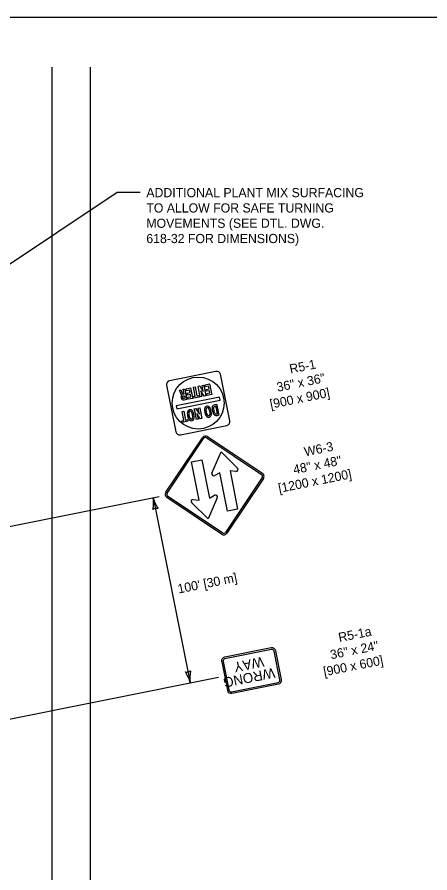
# Model space of a CAD drawing. Extents: x 49991.4 to 50021, y 49987.6 to 50011.4.
# Drawn here: x 50008.26 to 50010.96, y 49993.41 to 49999 of the extents above; entities that cross this region are included whole.
import ezdxf

# ---------------------------------------------------------------- set-up
doc = ezdxf.new("R2010")
doc.units = 0
for name, color, linetype in [('Level 1', 7, 'Continuous'), ('Level 2', 7, 'Continuous'), ('Level 3', 7, 'Continuous')]:
    doc.layers.add(name, color=color, linetype=linetype)

msp = doc.modelspace()

# ---------------------------------------------------------------- linework, layer by layer
at = {"layer": 'Level 1'}
for p, q in [((50008.4852, 49998.6725), (50008.4852, 49988.1855)), ((50008.7352, 49998.6725), (50008.7352, 49988.1855)), ((50009.5569, 49996.6843), (50009.2531, 49996.6231)), ((50009.6479, 49996.3607), (50009.5866, 49996.6648)), ((50009.2335, 49996.5936), (50009.2948, 49996.2896)), ((50009.3195, 49996.5619), (50009.3285, 49996.5641)), ((50009.3211, 49996.5577), (50009.3195, 49996.5619)), ((50009.3211, 49996.5577), (50009.3211, 49996.5577)), ((50009.3211, 49996.5577), (50009.3211, 49996.5577)), ((50009.324, 49996.5487), (50009.3211, 49996.5577)), ((50009.3285, 49996.5641), (50009.3361, 49996.5409)), ((50009.3435, 49996.567), (50009.3522, 49996.5686)), ((50009.3492, 49996.5382), (50009.3435, 49996.567)), ((50009.3522, 49996.5686), (50009.353, 49996.5641)), ((50009.353, 49996.5641), (50009.3548, 49996.555)), ((50009.3616, 49996.5706), (50009.391, 49996.5767)), ((50009.3644, 49996.5576), (50009.3616, 49996.5706)), ((50009.3849, 49996.5616), (50009.3644, 49996.5576)), ((50009.3883, 49996.5453), (50009.3849, 49996.5616)), ((50009.391, 49996.5767), (50009.3924, 49996.5682)), ((50009.3924, 49996.5682), (50009.3972, 49996.5446)), ((50009.4101, 49996.5804), (50009.421, 49996.5825)), ((50009.4218, 49996.5217), (50009.4101, 49996.5804)), ((50009.421, 49996.5825), (50009.4328, 49996.524)), ((50009.4405, 49996.5865), (50009.4507, 49996.5885)), ((50009.4429, 49996.5737), (50009.4405, 49996.5865)), ((50009.4544, 49996.5171), (50009.4429, 49996.5737)), ((50009.4507, 49996.5885), (50009.4576, 49996.5775)), ((50009.4794, 49996.5222), (50009.4573, 49996.5566)), ((50009.4573, 49996.5566), (50009.4649, 49996.5192)), ((50009.4576, 49996.5775), (50009.4741, 49996.5518)), ((50009.4661, 49996.5916), (50009.4767, 49996.5937)), ((50009.4686, 49996.5788), (50009.4661, 49996.5916)), ((50009.4741, 49996.5518), (50009.4686, 49996.5788)), ((50009.4767, 49996.5937), (50009.4792, 49996.5809)), ((50009.4792, 49996.5809), (50009.4886, 49996.535)), ((50009.4862, 49996.5957), (50009.5153, 49996.6018)), ((50009.4889, 49996.5827), (50009.4862, 49996.5957)), ((50009.5094, 49996.5869), (50009.4889, 49996.5827)), ((50009.4935, 49996.5666), (50009.5128, 49996.5706)), ((50009.4962, 49996.5538), (50009.4935, 49996.5666)), ((50009.5153, 49996.5576), (50009.4962, 49996.5538)), ((50009.5128, 49996.5706), (50009.5094, 49996.5869)), ((50009.5153, 49996.6018), (50009.517, 49996.5933)), ((50009.5181, 49996.5436), (50009.5153, 49996.5576)), ((50009.517, 49996.5933), (50009.5217, 49996.5699)), ((50009.5217, 49996.5699), (50009.5233, 49996.5618)), ((50009.5233, 49996.5618), (50009.5277, 49996.5405)), ((50009.5808, 49996.5157), (50009.2967, 49996.4584)), ((50009.3243, 49996.548), (50009.324, 49996.5487)), ((50009.3271, 49996.5384), (50009.3243, 49996.548)), ((50009.3271, 49996.5384), (50009.3271, 49996.5382)), ((50009.3291, 49996.5342), (50009.3271, 49996.5382)), ((50009.3298, 49996.533), (50009.3291, 49996.5342)), ((50009.3327, 49996.5301), (50009.3298, 49996.533)), ((50009.3301, 49996.516), (50009.3304, 49996.5176)), ((50009.3309, 49996.5116), (50009.3301, 49996.516)), ((50009.3304, 49996.5176), (50009.3308, 49996.5213)), ((50009.3308, 49996.5215), (50009.3311, 49996.5225)), ((50009.3308, 49996.5215), (50009.3308, 49996.5213)), ((50009.3312, 49996.5088), (50009.3309, 49996.5116)), ((50009.3311, 49996.5225), (50009.3324, 49996.5254)), ((50009.3322, 49996.5069), (50009.3312, 49996.5088)), ((50009.3334, 49996.5036), (50009.3322, 49996.5069)), ((50009.3324, 49996.5254), (50009.3343, 49996.5281)), ((50009.3358, 49996.529), (50009.3327, 49996.5301)), ((50009.3339, 49996.5023), (50009.3334, 49996.5036)), ((50009.3343, 49996.5281), (50009.3358, 49996.529)), ((50009.3379, 49996.4979), (50009.3343, 49996.5021)), ((50009.3361, 49996.5409), (50009.338, 49996.5379)), ((50009.338, 49996.5379), (50009.3401, 49996.5369)), ((50009.3395, 49996.5187), (50009.3404, 49996.5212)), ((50009.3396, 49996.5171), (50009.3395, 49996.5187)), ((50009.3396, 49996.5133), (50009.3396, 49996.5171)), ((50009.3407, 49996.5108), (50009.3396, 49996.5133)), ((50009.3401, 49996.5369), (50009.3445, 49996.5373)), ((50009.3404, 49996.5212), (50009.3421, 49996.5224)), ((50009.341, 49996.5096), (50009.3407, 49996.5108)), ((50009.343, 49996.5076), (50009.341, 49996.5096)), ((50009.3421, 49996.5224), (50009.3443, 49996.5232)), ((50009.3447, 49996.507), (50009.343, 49996.5076)), ((50009.3441, 49996.5373), (50009.3492, 49996.5382)), ((50009.3451, 49996.5233), (50009.3443, 49996.5232)), ((50009.3475, 49996.5073), (50009.3447, 49996.507)), ((50009.3451, 49996.5233), (50009.352, 49996.5246)), ((50009.3526, 49996.5084), (50009.3471, 49996.5072)), ((50009.352, 49996.5246), (50009.3551, 49996.5088)), ((50009.3551, 49996.5088), (50009.3526, 49996.5084)), ((50009.3548, 49996.555), (50009.3549, 49996.554)), ((50009.3549, 49996.554), (50009.3661, 49996.4995)), ((50009.369, 49996.5416), (50009.3883, 49996.5453)), ((50009.3716, 49996.5288), (50009.369, 49996.5416)), ((50009.3908, 49996.5325), (50009.3716, 49996.5288)), ((50009.3737, 49996.5145), (50009.3936, 49996.5185)), ((50009.3762, 49996.5015), (50009.3737, 49996.5145)), ((50009.405, 49996.5072), (50009.3762, 49996.5015)), ((50009.3936, 49996.5185), (50009.3908, 49996.5325)), ((50009.3972, 49996.5446), (50009.3988, 49996.5367)), ((50009.3988, 49996.5367), (50009.4033, 49996.5154)), ((50009.4033, 49996.5154), (50009.405, 49996.5072)), ((50009.4086, 49996.5192), (50009.4218, 49996.5217)), ((50009.4111, 49996.5084), (50009.4086, 49996.5192)), ((50009.4479, 49996.5159), (50009.4111, 49996.5084)), ((50009.4328, 49996.524), (50009.4456, 49996.5267)), ((50009.4456, 49996.5267), (50009.4479, 49996.5159)), ((50009.4649, 49996.5192), (50009.4544, 49996.5171)), ((50009.4907, 49996.5244), (50009.4794, 49996.5222)), ((50009.4886, 49996.535), (50009.4907, 49996.5244)), ((50009.4982, 49996.5398), (50009.5181, 49996.5436)), ((50009.5007, 49996.5268), (50009.4982, 49996.5398)), ((50009.5295, 49996.5324), (50009.5007, 49996.5268)), ((50009.5277, 49996.5405), (50009.5295, 49996.5324)), ((50009.5848, 49996.4959), (50009.5808, 49996.5157)), ((50009.2967, 49996.4584), (50009.3006, 49996.4387)), ((50009.3006, 49996.4387), (50009.5848, 49996.4959)), ((50009.3422, 49996.4959), (50009.3379, 49996.4979)), ((50009.3462, 49996.4957), (50009.3422, 49996.4959)), ((50009.3498, 49996.496), (50009.3462, 49996.4957)), ((50009.3661, 49996.4995), (50009.3498, 49996.496)), ((50009.441, 49996.4436), (50009.4517, 49996.4457)), ((50009.4435, 49996.4308), (50009.441, 49996.4436)), ((50009.4517, 49996.4457), (50009.4542, 49996.4331)), ((50009.4851, 49996.4454), (50009.484, 49996.4439)), ((50009.484, 49996.4439), (50009.4841, 49996.4435)), ((50009.4892, 49996.4523), (50009.4851, 49996.4454)), ((50009.4977, 49996.4563), (50009.4892, 49996.4523)), ((50009.4999, 49996.4459), (50009.4953, 49996.4434)), ((50009.507, 49996.4558), (50009.4977, 49996.4563)), ((50009.5048, 49996.4456), (50009.4999, 49996.4459)), ((50009.5096, 49996.4416), (50009.5048, 49996.4456)), ((50009.5134, 49996.4512), (50009.507, 49996.4558)), ((50009.5152, 49996.45), (50009.5134, 49996.4512)), ((50009.5152, 49996.4498), (50009.5152, 49996.45)), ((50009.5156, 49996.4499), (50009.5152, 49996.4498)), ((50009.5185, 49996.4449), (50009.5156, 49996.4499)), ((50009.5216, 49996.4396), (50009.5185, 49996.4447)), ((50009.5325, 49996.4477), (50009.5316, 49996.4406)), ((50009.5334, 49996.4526), (50009.5325, 49996.4477)), ((50009.5395, 49996.4621), (50009.5333, 49996.4538)), ((50009.5333, 49996.4538), (50009.5334, 49996.4526)), ((50009.549, 49996.4654), (50009.5395, 49996.4621)), ((50009.5419, 49996.4483), (50009.5406, 49996.4387)), ((50009.5451, 49996.4526), (50009.5419, 49996.4483)), ((50009.5501, 49996.4547), (50009.5451, 49996.4526)), ((50009.5636, 49996.4685), (50009.549, 49996.4654)), ((50009.5568, 49996.456), (50009.5501, 49996.4547)), ((50009.5577, 49996.4527), (50009.5568, 49996.456)), ((50009.559, 49996.4461), (50009.5577, 49996.4527)), ((50009.5596, 49996.4436), (50009.559, 49996.4459)), ((50009.5622, 49996.4304), (50009.5596, 49996.4436)), ((50009.5637, 49996.4669), (50009.5636, 49996.4685)), ((50009.565, 49996.4602), (50009.5637, 49996.4669)), ((50009.5653, 49996.459), (50009.565, 49996.4602)), ((50009.5662, 49996.4545), (50009.5653, 49996.459)), ((50009.5676, 49996.4478), (50009.5662, 49996.4545)), ((50009.5679, 49996.4452), (50009.5676, 49996.4478)), ((50009.5708, 49996.4322), (50009.5679, 49996.4452)), ((50009.3356, 49996.4225), (50009.3468, 49996.4248)), ((50009.3477, 49996.3638), (50009.3356, 49996.4225)), ((50009.3468, 49996.4248), (50009.3585, 49996.3661)), ((50009.3704, 49996.4147), (50009.3697, 49996.4088)), ((50009.3697, 49996.4088), (50009.3697, 49996.4088)), ((50009.3697, 49996.4088), (50009.3701, 49996.4054)), ((50009.3701, 49996.4054), (50009.3712, 49996.3939)), ((50009.3705, 49996.4149), (50009.3704, 49996.4147)), ((50009.3714, 49996.4206), (50009.3705, 49996.4149)), ((50009.3712, 49996.3939), (50009.3749, 49996.3812)), ((50009.3724, 49996.4225), (50009.3713, 49996.421)), ((50009.3713, 49996.421), (50009.3714, 49996.4206)), ((50009.3714, 49996.4206), (50009.3714, 49996.4206)), ((50009.3767, 49996.4294), (50009.3724, 49996.4225)), ((50009.3852, 49996.4334), (50009.3767, 49996.4294)), ((50009.3799, 49996.4154), (50009.379, 49996.4069)), ((50009.379, 49996.4069), (50009.3804, 49996.3952)), ((50009.3826, 49996.4205), (50009.3799, 49996.4154)), ((50009.3804, 49996.3952), (50009.3837, 49996.3834)), ((50009.3872, 49996.423), (50009.3826, 49996.4205)), ((50009.3943, 49996.4329), (50009.3852, 49996.4334)), ((50009.3921, 49996.4227), (50009.3872, 49996.423)), ((50009.3971, 49996.4187), (50009.3921, 49996.4227)), ((50009.401, 49996.4284), (50009.3943, 49996.4329)), ((50009.4011, 49996.4113), (50009.3971, 49996.4187)), ((50009.4025, 49996.4271), (50009.401, 49996.4284)), ((50009.4044, 49996.4002), (50009.4011, 49996.4113)), ((50009.4027, 49996.4269), (50009.4025, 49996.4271)), ((50009.4029, 49996.4268), (50009.4027, 49996.4269)), ((50009.4058, 49996.4218), (50009.4029, 49996.4268)), ((50009.4057, 49996.3885), (50009.4044, 49996.4002)), ((50009.4048, 49996.3797), (50009.4057, 49996.3885)), ((50009.4092, 49996.4167), (50009.4058, 49996.4218)), ((50009.4101, 49996.4134), (50009.4092, 49996.4167)), ((50009.4092, 49996.4167), (50009.4092, 49996.4167)), ((50009.4134, 49996.4021), (50009.4101, 49996.4134)), ((50009.4101, 49996.4134), (50009.4101, 49996.4134)), ((50009.4135, 49996.4017), (50009.4134, 49996.4021)), ((50009.4147, 49996.3891), (50009.4135, 49996.4017)), ((50009.4149, 49996.387), (50009.4147, 49996.3891)), ((50009.4154, 49996.4385), (50009.4257, 49996.4407)), ((50009.4181, 49996.4257), (50009.4154, 49996.4385)), ((50009.4294, 49996.3693), (50009.4181, 49996.4257)), ((50009.4257, 49996.4407), (50009.4326, 49996.4295)), ((50009.4544, 49996.3742), (50009.4323, 49996.4086)), ((50009.4323, 49996.4086), (50009.4398, 49996.3711)), ((50009.4326, 49996.4295), (50009.449, 49996.4038)), ((50009.449, 49996.4038), (50009.4435, 49996.4308)), ((50009.4542, 49996.4331), (50009.4636, 49996.387)), ((50009.483, 49996.4378), (50009.4822, 49996.4317)), ((50009.4822, 49996.4317), (50009.4822, 49996.4317)), ((50009.4822, 49996.4317), (50009.4828, 49996.4283)), ((50009.4828, 49996.4283), (50009.4839, 49996.4169)), ((50009.4841, 49996.4435), (50009.483, 49996.4378)), ((50009.483, 49996.4378), (50009.483, 49996.4378)), ((50009.4839, 49996.4169), (50009.4876, 49996.4041)), ((50009.4841, 49996.4435), (50009.4841, 49996.4435)), ((50009.4876, 49996.4041), (50009.4876, 49996.4041)), ((50009.4876, 49996.4041), (50009.4882, 49996.4021)), ((50009.4882, 49996.4021), (50009.4887, 49996.4009)), ((50009.4887, 49996.4009), (50009.4916, 49996.396)), ((50009.4926, 49996.4383), (50009.4915, 49996.4298)), ((50009.4915, 49996.4298), (50009.493, 49996.4183)), ((50009.4916, 49996.396), (50009.4945, 49996.3911)), ((50009.4953, 49996.4434), (50009.4926, 49996.4383)), ((50009.493, 49996.4181), (50009.4962, 49996.4063)), ((50009.4945, 49996.3911), (50009.4949, 49996.3911)), ((50009.4949, 49996.3911), (50009.4949, 49996.3909)), ((50009.4949, 49996.3909), (50009.4967, 49996.3897)), ((50009.4962, 49996.4063), (50009.5006, 49996.3991)), ((50009.4967, 49996.3897), (50009.5032, 49996.3851)), ((50009.5006, 49996.3991), (50009.5053, 49996.3956)), ((50009.5053, 49996.3956), (50009.51, 49996.395)), ((50009.5135, 49996.4342), (50009.5096, 49996.4416)), ((50009.51, 49996.395), (50009.5144, 49996.3973)), ((50009.512, 49996.385), (50009.5203, 49996.3886)), ((50009.5171, 49996.4231), (50009.5135, 49996.4342)), ((50009.5144, 49996.3973), (50009.5175, 49996.4026)), ((50009.5182, 49996.4113), (50009.5171, 49996.4231)), ((50009.5175, 49996.4026), (50009.5182, 49996.4113)), ((50009.5203, 49996.3886), (50009.5247, 49996.3953)), ((50009.5218, 49996.4396), (50009.5216, 49996.4396)), ((50009.5226, 49996.4365), (50009.5218, 49996.4396)), ((50009.5228, 49996.4363), (50009.5226, 49996.4365)), ((50009.5261, 49996.425), (50009.5228, 49996.4363)), ((50009.5247, 49996.3953), (50009.5259, 49996.3972)), ((50009.5259, 49996.3972), (50009.5267, 49996.4029)), ((50009.5262, 49996.4246), (50009.5261, 49996.425)), ((50009.5274, 49996.412), (50009.5262, 49996.4246)), ((50009.5267, 49996.4029), (50009.5277, 49996.4091)), ((50009.5276, 49996.4101), (50009.5274, 49996.412)), ((50009.5277, 49996.4091), (50009.5276, 49996.4101)), ((50009.5316, 49996.4406), (50009.5318, 49996.438)), ((50009.5318, 49996.438), (50009.5338, 49996.4247)), ((50009.5338, 49996.4247), (50009.5339, 49996.4231)), ((50009.5339, 49996.4231), (50009.5378, 49996.4127)), ((50009.5378, 49996.4127), (50009.5394, 49996.4088)), ((50009.5394, 49996.4088), (50009.5421, 49996.4053)), ((50009.5406, 49996.4387), (50009.5425, 49996.426)), ((50009.5421, 49996.4053), (50009.5449, 49996.4017)), ((50009.5424, 49996.4266), (50009.543, 49996.4251)), ((50009.5425, 49996.426), (50009.5464, 49996.4153)), ((50009.5449, 49996.4017), (50009.5458, 49996.4006)), ((50009.5458, 49996.4006), (50009.547, 49996.3993)), ((50009.5464, 49996.4153), (50009.551, 49996.4088)), ((50009.547, 49996.3993), (50009.5552, 49996.3957)), ((50009.551, 49996.4088), (50009.5557, 49996.4062)), ((50009.5552, 49996.3957), (50009.5643, 49996.3966)), ((50009.5557, 49996.4062), (50009.5605, 49996.4063)), ((50009.5605, 49996.4063), (50009.5666, 49996.4075)), ((50009.5623, 49996.429), (50009.5621, 49996.4306)), ((50009.5646, 49996.418), (50009.5623, 49996.4288)), ((50009.5643, 49996.3966), (50009.5773, 49996.3991)), ((50009.5654, 49996.4142), (50009.5646, 49996.418)), ((50009.5662, 49996.4103), (50009.5654, 49996.4142)), ((50009.5666, 49996.4075), (50009.5662, 49996.4101)), ((50009.571, 49996.4307), (50009.5708, 49996.4322)), ((50009.5733, 49996.4198), (50009.571, 49996.4307)), ((50009.574, 49996.4159), (50009.5733, 49996.4198)), ((50009.5748, 49996.4119), (50009.574, 49996.4159)), ((50009.5757, 49996.4078), (50009.5748, 49996.4119)), ((50009.576, 49996.4068), (50009.5757, 49996.4078)), ((50009.5763, 49996.4051), (50009.576, 49996.4068)), ((50009.5772, 49996.4001), (50009.5763, 49996.4051)), ((50009.5773, 49996.3991), (50009.5772, 49996.4001)), ((50009.3345, 49996.3612), (50009.3477, 49996.3638)), ((50009.3368, 49996.3506), (50009.3345, 49996.3612)), ((50009.3736, 49996.3579), (50009.3368, 49996.3506)), ((50009.3585, 49996.3661), (50009.3713, 49996.3687)), ((50009.3713, 49996.3687), (50009.3736, 49996.3579)), ((50009.3749, 49996.3812), (50009.3749, 49996.3812)), ((50009.3749, 49996.3812), (50009.3755, 49996.379)), ((50009.3755, 49996.379), (50009.376, 49996.378)), ((50009.376, 49996.378), (50009.3791, 49996.3731)), ((50009.3791, 49996.3731), (50009.382, 49996.3682)), ((50009.382, 49996.3682), (50009.3823, 49996.368)), ((50009.3823, 49996.368), (50009.3823, 49996.3678)), ((50009.3823, 49996.3678), (50009.384, 49996.3668)), ((50009.3837, 49996.3834), (50009.3879, 49996.3762)), ((50009.384, 49996.3668), (50009.3905, 49996.3622)), ((50009.3879, 49996.3762), (50009.3926, 49996.3727)), ((50009.3905, 49996.3622), (50009.3995, 49996.3619)), ((50009.3926, 49996.3727), (50009.3975, 49996.3722)), ((50009.3975, 49996.3722), (50009.4017, 49996.3744)), ((50009.3995, 49996.3619), (50009.4078, 49996.3657)), ((50009.4017, 49996.3744), (50009.4048, 49996.3797)), ((50009.4078, 49996.3657), (50009.412, 49996.3724)), ((50009.412, 49996.3724), (50009.4134, 49996.3743)), ((50009.4134, 49996.3743), (50009.4142, 49996.38)), ((50009.4142, 49996.38), (50009.415, 49996.386)), ((50009.415, 49996.386), (50009.4149, 49996.387)), ((50009.4398, 49996.3711), (50009.4294, 49996.3693)), ((50009.4656, 49996.3765), (50009.4544, 49996.3742)), ((50009.4636, 49996.387), (50009.4656, 49996.3765)), ((50009.5032, 49996.3851), (50009.512, 49996.385)), ((50009.3243, 49996.27), (50009.6283, 49996.3313)), ((50009.2289, 49995.8938), (50009.4683, 49996.2508)), ((50009.2374, 49995.888), (50009.4765, 49996.2453)), ((50009.4973, 49996.2496), (50009.8548, 49996.0104)), ((50009.5028, 49996.2577), (50009.8603, 49996.0187)), ((50009.5307, 49996.0195), (50009.5902, 49996.1574)), ((50009.5902, 49996.1574), (50009.6978, 49996.0526)), ((50009.3974, 49996.0932), (50009.4641, 49996.1063)), ((50009.4472, 49995.8427), (50009.3974, 49996.0932)), ((50009.4643, 49996.1064), (50009.5139, 49995.8558)), ((50009.5825, 49996.0219), (50009.549, 49996.0031)), ((50009.6319, 49995.7713), (50009.5825, 49996.0219)), ((50009.6871, 49996.0305), (50009.6492, 49996.0351)), ((50009.6492, 49996.0351), (50009.6986, 49995.7844)), ((50009.8589, 49995.9895), (50009.6197, 49995.6321)), ((50009.867, 49995.984), (50009.6278, 49995.6266)), ((50009.5931, 49995.6198), (50009.2359, 49995.8591)), ((50009.5988, 49995.628), (50009.2415, 49995.8673)), ((50009.409, 49995.8469), (50009.4472, 49995.8427)), ((50009.5654, 49995.8581), (50009.5061, 49995.7201)), ((50009.5139, 49995.8558), (50009.5473, 49995.8743)), ((50009.5061, 49995.7201), (50009.3986, 49995.8249)), ((50009.6986, 49995.7844), (50009.6319, 49995.7713)), ((50009.918, 49994.8766), (50009.6141, 49994.8158)), ((50009.92, 49994.8668), (50009.616, 49994.806)), ((50009.9749, 49994.6687), (50009.9377, 49994.855)), ((50009.9847, 49994.6706), (50009.9475, 49994.857)), ((50009.5945, 49994.7864), (50009.6317, 49994.6)), ((50009.6043, 49994.7883), (50009.6415, 49994.602)), ((50009.6592, 49994.5902), (50009.9632, 49994.651)), ((50009.6611, 49994.5804), (50009.9651, 49994.6412))]:
    msp.add_line(p, q, dxfattribs=at)
msp.add_lwpolyline([(49999.3835, 49998.9992), (50016.7501, 49998.9992), (50016.7501, 49987.7988), (49999.3835, 49987.7988)], close=True, dxfattribs=at)
msp.add_circle((50009.4407, 49996.4773), 0.1699, dxfattribs=at)
for centre, radius, start, end in [((50009.5619, 49996.6598), 0.025, 11.4067, 101.4067), ((50009.258, 49996.5985), 0.025, 101.4067, 191.4067), ((50009.6233, 49996.3559), 0.025, 281.4067, 11.4067), ((50009.3193, 49996.2945), 0.025, 191.4067, 281.4067), ((50009.4891, 49996.2369), 0.025, 56.1986, 146.1982), ((50009.4891, 49996.2369), 0.015, 56.1986, 146.1982), ((50009.6887, 49996.0432), 0.0129, 334.4788, 45.7176), ((50009.5427, 49996.0143), 0.0129, 156.7831, 227.9145), ((50009.5427, 49996.0143), 0.0129, 227.9176, 299.1564), ((50009.6887, 49996.0432), 0.0129, 263.24, 334.4757), ((50009.8464, 49995.9977), 0.015, 326.1979, 56.1982), ((50009.8464, 49995.9977), 0.025, 326.1979, 56.1982), ((50009.2499, 49995.8796), 0.025, 146.1982, 236.1982), ((50009.2499, 49995.8796), 0.015, 146.1982, 236.1982), ((50009.4076, 49995.8341), 0.0129, 154.4788, 225.7176), ((50009.4076, 49995.8341), 0.0129, 83.24, 154.4757), ((50009.5536, 49995.863), 0.0129, 47.9176, 119.1564), ((50009.5536, 49995.863), 0.0129, 336.7831, 47.9145), ((50009.6072, 49995.6404), 0.025, 236.1982, 326.1982), ((50009.6072, 49995.6404), 0.015, 236.1982, 326.1982), ((50009.9229, 49994.8521), 0.025, 11.3105, 101.3105), ((50009.9229, 49994.8521), 0.015, 11.3105, 101.3105), ((50009.6189, 49994.7913), 0.025, 101.3105, 191.3105), ((50009.6189, 49994.7913), 0.015, 101.3105, 191.3105), ((50009.9601, 49994.6657), 0.015, 281.3105, 11.3105), ((50009.9601, 49994.6657), 0.025, 281.3105, 11.3105), ((50009.6562, 49994.6049), 0.025, 191.3105, 281.3105), ((50009.6562, 49994.6049), 0.015, 191.3105, 281.3105)]:
    msp.add_arc(centre, radius, start, end, dxfattribs=at)
at = {"layer": 'Level 3'}
for p, q in [((50008.912, 49997.8523), (50007.6889, 49997.0383)), ((50009.062, 49997.8523), (50008.912, 49997.8523)), ((50007.4715, 49995.524), (50009.1861, 49995.8669)), ((50009.1469, 49995.8591), (50009.389, 49994.6484)), ((50007.7137, 49994.3132), (50009.5739, 49994.6854))]:
    msp.add_line(p, q, dxfattribs=at)
for centre, radius, start, end in [((50008.9273, 49995.8245), 0.2223, 348.7641, 8.9477), ((50009.3728, 49995.916), 0.233, 194.1354, 213.3853), ((50009.172, 49995.7334), 0.0548, 83.447, 119.1693), ((50009.3638, 49994.7741), 0.0548, 263.446, 299.1684), ((50009.163, 49994.5915), 0.233, 14.1345, 33.3844), ((50009.6086, 49994.6829), 0.2223, 168.7632, 188.9467)]:
    msp.add_arc(centre, radius, start, end, dxfattribs=at)

# ---------------------------------------------------------------- texts
at = {"layer": 'Level 1'}
for s, p in [('WAY', (50009.8633, 49994.8197)), ('WRONG', (50009.9351, 49994.7474))]:
    msp.add_text(s, height=0.065, rotation=191.3105, dxfattribs=at).set_placement(p)
at = {"layer": 'Level 2'}
for s, p in [('ADDITIONAL PLANT MIX SURFACING ', (50009.102, 49997.8223)), ('TO ALLOW FOR SAFE TURNING', (50009.102, 49997.7223)), ('MOVEMENTS (SEE DTL. DWG.', (50009.102, 49997.6223)), ('618-32 FOR DIMENSIONS)', (50009.102, 49997.5223))]:
    msp.add_text(s, height=0.06, dxfattribs=at).set_placement(p)
for s, height, rotation, p in [('R5-1', 0.06, 11.3957, (50010.0443, 49996.6693)), ('36" x 36"', 0.06, 11.3957, (50009.9605, 49996.5506)), ('[900 x 900]', 0.059999, 11.3957, (50009.916, 49996.4397)), ('W6-3', 0.06, 11.3957, (50010.1405, 49996.1282)), ('48" x 48"', 0.06, 11.3957, (50010.0683, 49996.0118)), ('[1200 x 1200]', 0.059999, 11.3957, (50009.971, 49995.8902)), ("100' [30 m]", 0.06, 11.3105, (50009.3131, 49995.2321)), ('R5-1a', 0.06, 11.3105, (50010.3639, 49994.9147)), ('36" x 24"', 0.06, 11.3105, (50010.3103, 49994.8021)), ('[900 x 600]', 0.06, 11.3105, (50010.2656, 49994.6912))]:
    msp.add_text(s, height=height, rotation=rotation, dxfattribs=at).set_placement(p)

doc.saveas('drawing.dxf')
